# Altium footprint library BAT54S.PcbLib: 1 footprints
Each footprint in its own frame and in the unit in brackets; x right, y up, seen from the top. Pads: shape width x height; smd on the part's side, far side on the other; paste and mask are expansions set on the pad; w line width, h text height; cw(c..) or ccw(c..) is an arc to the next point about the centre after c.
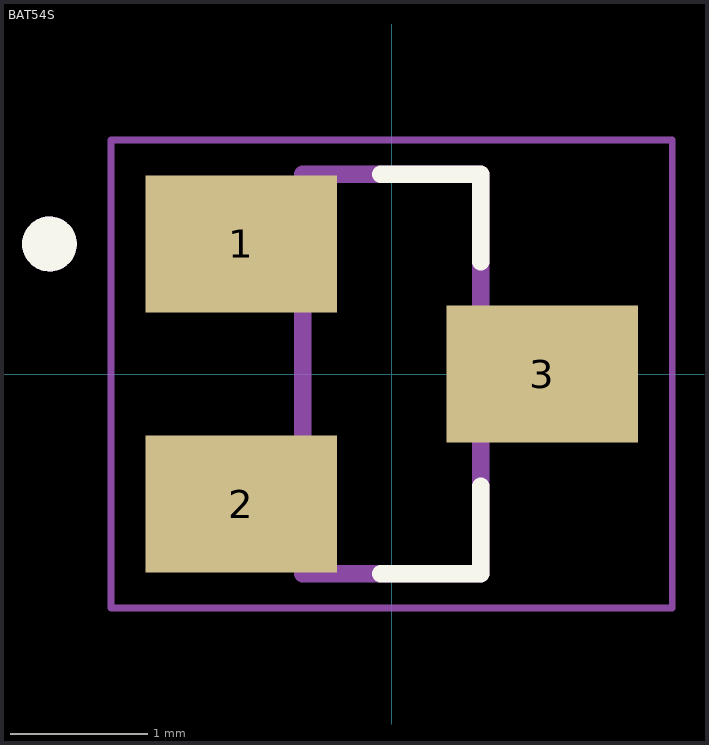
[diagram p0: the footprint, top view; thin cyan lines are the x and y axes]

## BAT54S [mm]
height 1.2
pads (3):
  rect 1.4x1 smd: 1(-1.1,0.95) 2(-1.1,-0.95) 3(1.1,0)
Top Overlay:
  circle w0.2: c-2.5,0.95 r0.1
  lines w0.127: -0.08,-1.46 0.65,-1.46 0.65,-0.82 ; -0.08,1.46 0.65,1.46 0.65,0.82
Mechanical 13:
  circle w0.2: c-2.5,0.95 r0.1
  lines w0.127: -0.65,-1.46 -0.65,1.46 0.65,1.46 0.65,-1.46 -0.65,-1.46
Mechanical 15:
  lines w0.05: -2.05,-1.71 2.05,-1.71 2.05,1.71 -2.05,1.71 -2.05,-1.71
3D body "BAT54S.STEP": height 1.2, standoff 0, extent -1.284,-1.444 1.116,1.476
